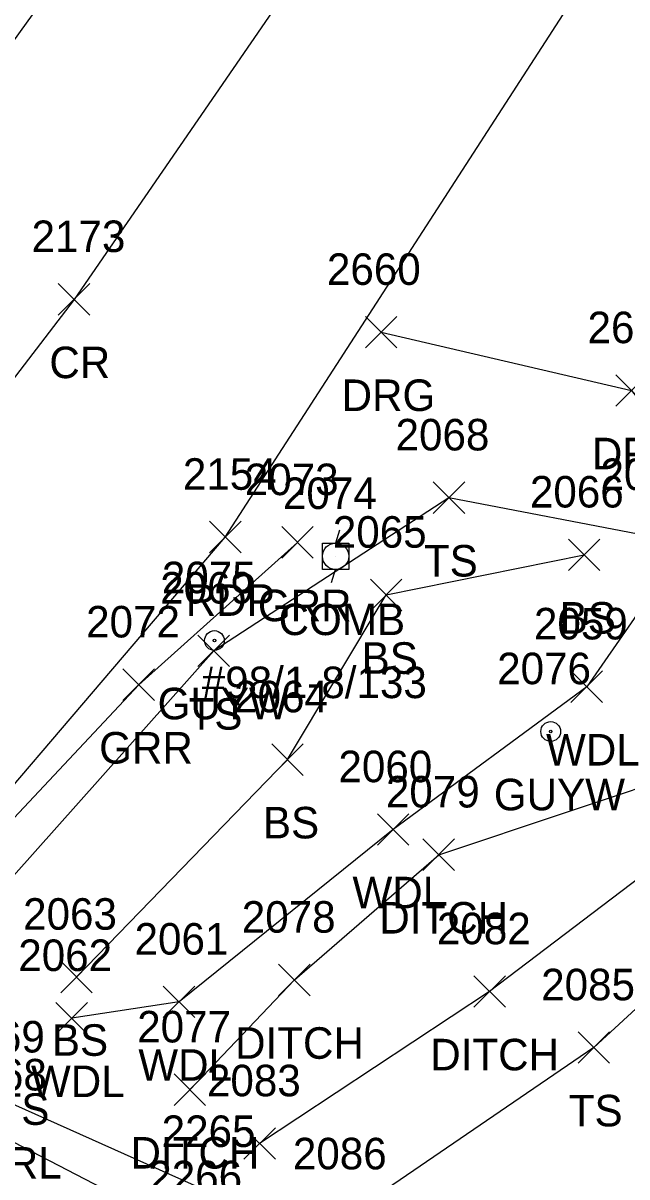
# Model space of a CAD drawing. Extents: x 1633660 to 1636532, y 388643 to 392631.
# Drawn here: x 1634790 to 1634828.3, y 389221.9 to 389295.1 of the extents above; entities that cross this region are included whole.
import ezdxf

# ---------------------------------------------------------------- set-up
doc = ezdxf.new("R2010")
doc.units = 0
for name, color, linetype in [('D_A', 7, 'Continuous'), ('D_I', 7, 'Continuous'), ('D_TIC', 7, 'Continuous'), ('DD', 7, 'Continuous'), ('L_A', 7, 'Continuous'), ('L_I', 7, 'Continuous'), ('L_TIC', 7, 'Continuous'), ('LAWA', 7, 'Continuous'), ('LAWE', 7, 'Continuous'), ('LELB', 7, 'Continuous'), ('P_A', 7, 'Continuous'), ('P_I', 7, 'Continuous'), ('P_TIC', 7, 'Continuous'), ('PET', 7, 'Continuous'), ('PRC', 7, 'Continuous'), ('R_A', 7, 'Continuous'), ('R_C', 7, 'Continuous'), ('R_I', 7, 'Continuous'), ('R_TIC', 7, 'Continuous'), ('RDG', 7, 'Continuous'), ('RGR', 7, 'Continuous'), ('U_A', 7, 'Continuous'), ('U_C', 7, 'Continuous'), ('U_I', 7, 'Continuous'), ('UP', 7, 'Continuous'), ('UPGW', 7, 'Continuous')]:
    doc.layers.add(name, color=color, linetype=linetype)

msp = doc.modelspace()

# ---------------------------------------------------------------- linework, layer by layer
at = {"layer": 'D_TIC'}
for points in [[(1634815.371, 389241.363), (1634817.371, 389243.363)], [(1634817.371, 389241.363), (1634815.371, 389243.363)], [(1634806.22, 389233.419), (1634808.22, 389235.419)], [(1634808.22, 389233.419), (1634806.22, 389235.419)], [(1634818.598, 389232.686), (1634820.598, 389234.686)], [(1634820.598, 389232.686), (1634818.598, 389234.686)], [(1634799.587, 389226.455), (1634801.587, 389228.455)], [(1634801.587, 389226.455), (1634799.587, 389228.455)], [(1634804.013, 389223.04), (1634806.013, 389225.04)], [(1634806.013, 389223.04), (1634804.013, 389225.04)]]:
    msp.add_lwpolyline(points, dxfattribs=at)
at = {"layer": 'DD'}
msp.add_lwpolyline([(1634800.587, 389227.455), (1634807.22, 389234.419), (1634816.371, 389242.363), (1634832.836, 389247.853), (1634835.101, 389245.475), (1634819.598, 389233.686), (1634805.013, 389224.04)], dxfattribs=at)
at = {"layer": 'L_TIC'}
for points in [[(1634816.023, 389264.015), (1634818.023, 389266.015)], [(1634818.023, 389264.015), (1634816.023, 389266.015)], [(1634824.598, 389260.394), (1634826.598, 389262.394)], [(1634826.598, 389260.394), (1634824.598, 389262.394)], [(1634812.042, 389257.845), (1634814.042, 389259.845)], [(1634814.042, 389257.845), (1634812.042, 389259.845)], [(1634801.099, 389254.301), (1634803.099, 389256.301)], [(1634803.099, 389254.301), (1634801.099, 389256.301)], [(1634824.76, 389252.025), (1634826.76, 389254.025)], [(1634826.76, 389252.025), (1634824.76, 389254.025)], [(1634805.783, 389247.4), (1634807.783, 389249.4)], [(1634807.783, 389247.4), (1634805.783, 389249.4)], [(1634812.484, 389242.966), (1634814.484, 389244.966)], [(1634814.484, 389242.966), (1634812.484, 389244.966)], [(1634792.398, 389233.607), (1634794.398, 389235.607)], [(1634794.398, 389233.607), (1634792.398, 389235.607)], [(1634798.901, 389232.028), (1634800.901, 389234.028)], [(1634800.901, 389232.028), (1634798.901, 389234.028)], [(1634792.094, 389230.987), (1634794.094, 389232.987)], [(1634794.094, 389230.987), (1634792.094, 389232.987)], [(1634825.209, 389229.13), (1634827.209, 389231.13)], [(1634827.209, 389229.13), (1634825.209, 389231.13)]]:
    msp.add_lwpolyline(points, dxfattribs=at)
at = {"layer": 'LAWA'}
msp.add_lwpolyline([(1634811.654, 389038.972), (1634818.433, 389066.627), (1634837.849, 389085.946), (1634849.332, 389112.531), (1634851.418, 389137.052), (1634857.154, 389168.507), (1634851.262, 389192.249), (1634842.559, 389222.615), (1634839.168, 389244.566), (1634831.585, 389261.414), (1634825.76, 389253.025), (1634813.484, 389243.966), (1634799.901, 389233.028), (1634793.094, 389231.987)], dxfattribs=at)
at = {"layer": 'LAWE'}
msp.add_lwpolyline([(1634485.266, 388945.868), (1634504.196, 388941.237), (1634525.532, 388940.734), (1634548.507, 388932.941), (1634584.664, 388919.999), (1634598.752, 388914.409), (1634618.803, 388928.878), (1634638.301, 388944.913), (1634660.99, 388957.079), (1634677.576, 388983.238), (1634696.949, 389006.397), (1634707.364, 389033.308), (1634727.928, 389056.715), (1634749.887, 389078.696), (1634762.92, 389095.064), (1634797.897, 389102.54), (1634816.332, 389112.037), (1634824.178, 389130.773), (1634824.184, 389150.648), (1634818.446, 389174.952), (1634815.049, 389205.919), (1634802.108, 389220.823), (1634788.756, 389226.818)], dxfattribs=at)
at = {"layer": 'LELB'}
for points in [[(1634830.021, 389262.502), (1634817.023, 389265.015), (1634802.099, 389255.301), (1634782.182, 389232.916)], [(1634793.398, 389234.607), (1634806.783, 389248.4), (1634813.042, 389258.845), (1634825.598, 389261.394)], [(1634837.414, 389240.465), (1634826.209, 389230.13), (1634810.516, 389219.404), (1634822.419, 389209.639), (1634833.611, 389184.58), (1634846.556, 389159.137)], [(1634633.695, 388947.021), (1634652.585, 388956.595), (1634671.201, 388984.135), (1634685.401, 389000.206), (1634693.628, 389014.81), (1634704.343, 389035.4), (1634725.63, 389062.246), (1634746.904, 389081.237), (1634759.284, 389096.885), (1634788.685, 389102.007), (1634810.124, 389114.596), (1634818.922, 389123.639), (1634818.088, 389148.686), (1634815.048, 389173.408), (1634811.187, 389202.43), (1634801.315, 389217.947), (1634788.875, 389224.41)]]:
    msp.add_lwpolyline(points, dxfattribs=at)
at = {"layer": 'P_TIC'}
for points in [[(1634792.243, 389276.601), (1634794.243, 389278.601)], [(1634794.243, 389276.601), (1634792.243, 389278.601)], [(1634801.838, 389261.519), (1634803.838, 389263.519)], [(1634803.838, 389261.519), (1634801.838, 389263.519)]]:
    msp.add_lwpolyline(points, dxfattribs=at)
at = {"layer": 'PET'}
for points in [[(1634921.002, 389515.03), (1634899.802, 389480.53), (1634874.189, 389437.174), (1634846.922, 389390.201), (1634820.403, 389343.783), (1634802.56, 389312.32), (1634782.667, 389284.651), (1634768.754, 389267.285)], [(1634759.683, 389257.144), (1634768.683, 389246.682), (1634778.862, 389234.437), (1634802.838, 389262.519), (1634835.45, 389312.997), (1634837.672, 389319.49), (1634869.562, 389375.262), (1634896.662, 389421.501), (1634916.947, 389456.153), (1634943.654, 389500.194)]]:
    msp.add_lwpolyline(points, dxfattribs=at)
at = {"layer": 'PRC'}
msp.add_lwpolyline([(1634932.003, 389507.764), (1634911.044, 389472.797), (1634886.741, 389431.158), (1634857.717, 389381.065), (1634832.11, 389337.094), (1634812.294, 389305.303), (1634793.243, 389277.601), (1634779.167, 389259.209), (1634770.349, 389248.304)], dxfattribs=at)
at = {"layer": 'R_TIC'}
for points in [[(1634811.724, 389274.517), (1634813.724, 389276.517)], [(1634813.724, 389274.517), (1634811.724, 389276.517)], [(1634827.6, 389270.82), (1634829.6, 389272.82)], [(1634829.6, 389270.82), (1634827.6, 389272.82)], [(1634806.413, 389261.179), (1634808.413, 389263.179)], [(1634808.413, 389261.179), (1634806.413, 389263.179)], [(1634796.348, 389252.149), (1634798.348, 389254.149)], [(1634798.348, 389252.149), (1634796.348, 389254.149)]]:
    msp.add_lwpolyline(points, dxfattribs=at)
at = {"layer": 'RDG'}
msp.add_lwpolyline([(1634812.724, 389275.517), (1634828.6, 389271.82), (1634840.175, 389256.846), (1634851.532, 389227.835), (1634860.916, 389199.082), (1634872.346, 389171.963)], dxfattribs=at)
at = {"layer": 'RGR'}
msp.add_lwpolyline([(1634779.621, 389234.228), (1634797.348, 389253.149), (1634807.413, 389262.179)], dxfattribs=at)
at = {"layer": 'UP'}
for p, q in [((1634810.082, 389262.966), (1634809.832, 389262.133)), ((1634808.999, 389260.466), (1634808.999, 389262.133)), ((1634808.999, 389262.133), (1634810.665, 389262.133)), ((1634810.665, 389262.133), (1634810.665, 389260.466)), ((1634809.832, 389261.3), (1634809.832, 389261.3)), ((1634810.665, 389260.466), (1634808.999, 389260.466)), ((1634809.582, 389259.633), (1634809.832, 389260.466))]:
    msp.add_line(p, q, dxfattribs=at)
msp.add_circle((1634809.832, 389261.3), 0.833, dxfattribs=at)
at = {"layer": 'UPGW'}
for centre, radius in [((1634802.15, 389255.956), 0.625), ((1634802.15, 389255.956), 0.0833), ((1634823.474, 389250.183), 0.625), ((1634823.474, 389250.183), 0.0833)]:
    msp.add_circle(centre, radius, dxfattribs=at)

# ---------------------------------------------------------------- texts
at = {"layer": 'D_A'}
for p in [(1634812.607, 389237.363), (1634803.456, 389229.419), (1634815.835, 389228.686), (1634796.823, 389222.455)]:
    msp.add_text('DITCH', height=2, dxfattribs=at).set_placement(p)
at = {"layer": 'D_I'}
for s, p in [('2079', (1634813.024, 389245.363)), ('2078', (1634803.881, 389237.419)), ('2082', (1634816.26, 389236.686)), ('2077', (1634797.249, 389230.455)), ('2083', (1634801.674, 389227.04))]:
    msp.add_text(s, height=2, dxfattribs=at).set_placement(p)
at = {"layer": 'L_A'}
for s, p in [('TS', (1634815.433, 389260.015)), ('BS', (1634824.039, 389256.394)), ('BS', (1634811.483, 389253.845)), ('TS', (1634800.508, 389250.301)), ('WDL', (1634823.178, 389248.025)), ('BS', (1634805.224, 389243.4)), ('WDL', (1634810.902, 389238.966)), ('BS', (1634791.839, 389229.607)), ('WDL', (1634797.319, 389228.028)), ('WDL', (1634790.511, 389226.987)), ('TS', (1634824.619, 389225.13)), ('RVRL', (1634785.323, 389221.818))]:
    msp.add_text(s, height=2, dxfattribs=at).set_placement(p)
at = {"layer": 'L_I'}
for s, p in [('2068', (1634813.637, 389268.015)), ('2067', (1634826.635, 389265.502)), ('2066', (1634822.157, 389264.394)), ('2065', (1634809.656, 389261.845)), ('2069', (1634798.705, 389258.301)), ('2059', (1634822.414, 389256.025)), ('2064', (1634803.397, 389251.4)), ('2060', (1634810.012, 389246.966)), ('2063', (1634790.012, 389237.607)), ('2061', (1634797.082, 389236.028)), ('2062', (1634789.708, 389234.987)), ('2085', (1634822.871, 389233.13)), ('2269', (1634785.441, 389229.818)), ('2268', (1634785.568, 389227.41)), ('2265', (1634798.801, 389223.823)), ('2086', (1634807.123, 389222.404)), ('2266', (1634797.953, 389220.947))]:
    msp.add_text(s, height=2, dxfattribs=at).set_placement(p)
at = {"layer": 'P_A'}
for s, p in [('CR', (1634791.676, 389272.601)), ('RDP', (1634800.326, 389257.519))]:
    msp.add_text(s, height=2, dxfattribs=at).set_placement(p)
at = {"layer": 'P_I'}
for s, p in [('2173', (1634790.55, 389280.601)), ('2154', (1634800.145, 389265.519))]:
    msp.add_text(s, height=2, dxfattribs=at).set_placement(p)
at = {"layer": 'R_A'}
for s, p in [('DRG', (1634810.213, 389270.517)), ('DRG', (1634826.088, 389266.82)), ('GRR', (1634804.901, 389257.179)), ('GRR', (1634794.836, 389248.149))]:
    msp.add_text(s, height=2, dxfattribs=at).set_placement(p)
at = {"layer": 'R_C'}
msp.add_text('SGR W/ STEEL POSTS', height=2, dxfattribs=at).set_placement((1634762.85, 389225.228))
at = {"layer": 'R_I'}
for s, p in [('2660', (1634809.283, 389278.517)), ('2661', (1634825.812, 389274.82)), ('2073', (1634804.074, 389265.179)), ('2072', (1634794.009, 389256.149))]:
    msp.add_text(s, height=2, dxfattribs=at).set_placement(p)
at = {"layer": 'U_A'}
for s, p in [('COMB', (1634806.218, 389256.3)), ('GUYW', (1634798.544, 389250.956)), ('GUYW', (1634819.868, 389245.183))]:
    msp.add_text(s, height=2, dxfattribs=at).set_placement(p)
at = {"layer": 'U_C'}
msp.add_text('#98/1-8/133', height=2, dxfattribs=at).set_placement((1634801.344, 389252.3))
at = {"layer": 'U_I'}
for s, p in [('2074', (1634806.493, 389264.3)), ('2075', (1634798.812, 389258.956)), ('2076', (1634820.08, 389253.183))]:
    msp.add_text(s, height=2, dxfattribs=at).set_placement(p)

doc.saveas('drawing.dxf')
